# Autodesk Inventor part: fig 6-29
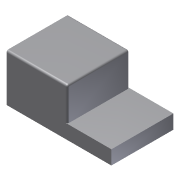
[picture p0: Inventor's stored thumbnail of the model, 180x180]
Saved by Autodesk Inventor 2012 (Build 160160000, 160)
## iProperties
Created: 2004-05
Part Number: fig 6-29
Document SubType Name: Modeling
Designer: CADCIM Technologies
Manufacturer: Standard
Standards Organization: Custom
Density: 1 g/cm^3
Material: Default
Author: CADCIM Technologies
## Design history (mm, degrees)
node "Sketch1"
sketch "Sketch2"
  geometry: L1 (0.098, 47.711)-(0.098, 0.049); L2 (0.098, 0.049)-(-105.483, 0.049); L3 (-105.483, 0.049)-(-105.483, 14.192); L4 (-105.483, 14.192)-(-61.139, 14.192); L5 (-61.139, 14.192)-(-61.139, 47.711); L6 (-61.139, 47.711)-(0.098, 47.711)
  constraints: 12 end point, 3 parallel, 2 perpendicular, 1 vertical
extrude "Extrusion1" new body sketch "Sketch2" stored distance "d0" = 62.5; taper "d1" = 0 deg
fillet "Fillet6" dims "d44" = 2, "d45" = 2, "d46" = 2, "d47" = 2, "d48" = 2, "d49" = 2
body "Solid1"
